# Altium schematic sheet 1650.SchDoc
size A4
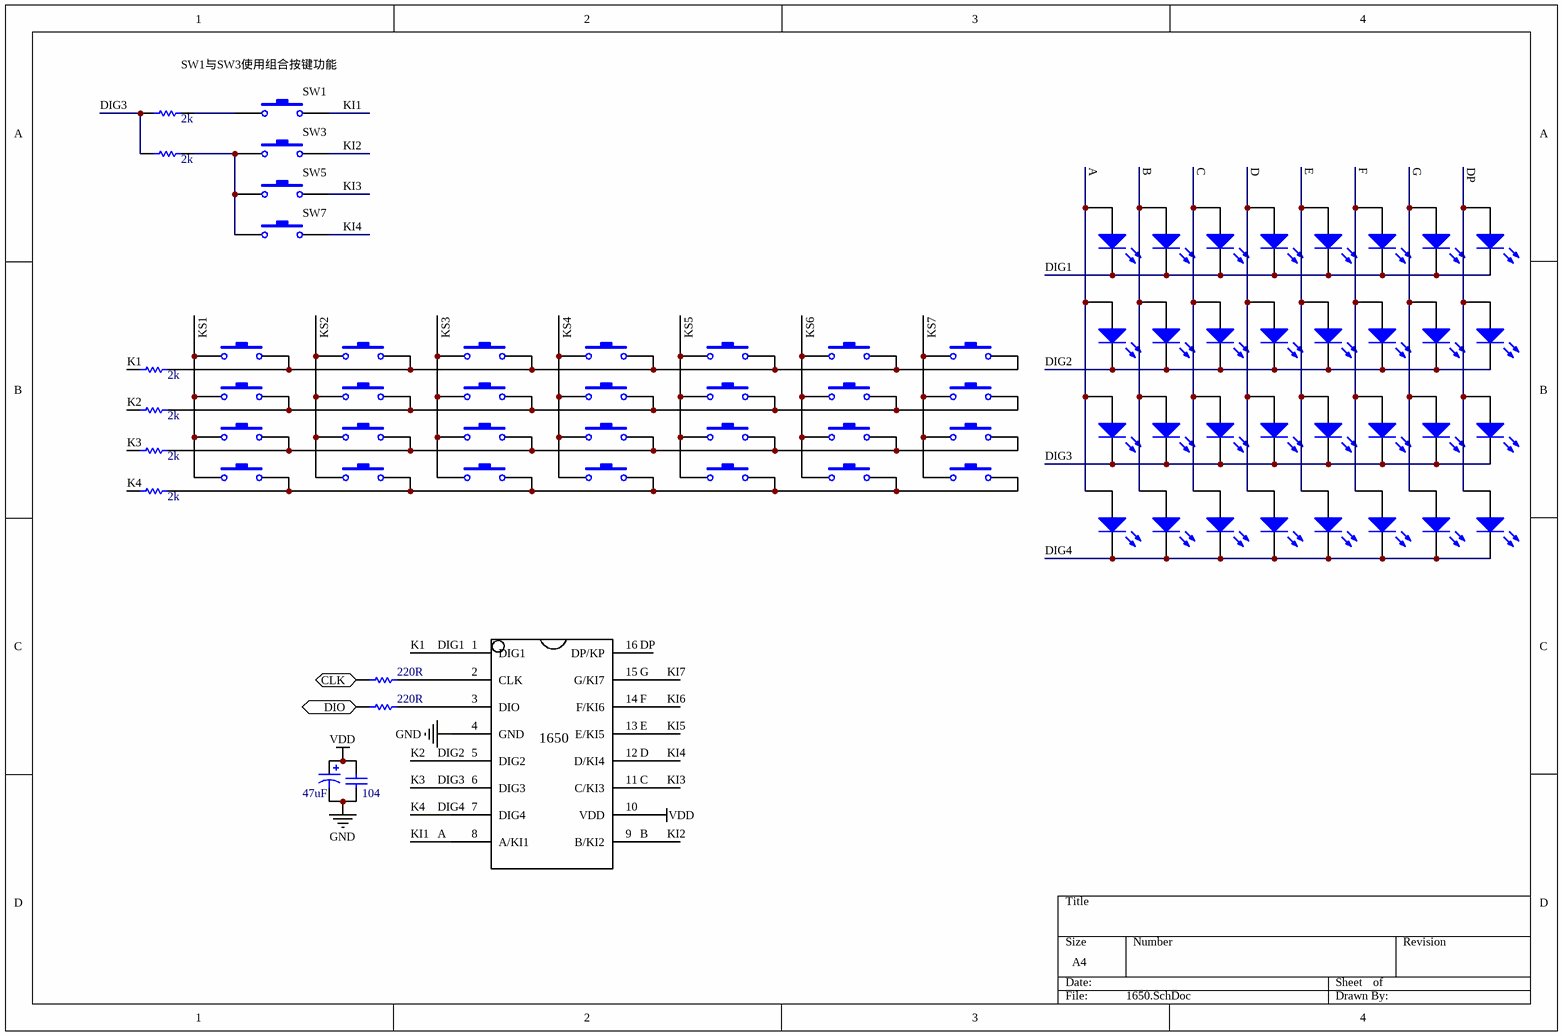
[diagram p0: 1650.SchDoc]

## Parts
(Parts that share a designator on the sheet are numbered #1, #2 ... from top to bottom, then left to right.)
*  Component_2  (value not drawn)
C6  value 104  [RAD-0.3]  (hidden comment: Cap)
C?  value 47uF  [RB7.6-15]  (hidden comment: Cap Pol1)
D?#1  LED0  [LED-0]  (value not drawn)
D?#2  LED0  [LED-0]  (value not drawn)
D?#3  LED0  [LED-0]  (value not drawn)
D?#4  LED0  [LED-0]  (value not drawn)
D?#5  LED0  [LED-0]  (value not drawn)
D?#6  LED0  [LED-0]  (value not drawn)
D?#7  LED0  [LED-0]  (value not drawn)
D?#8  LED0  [LED-0]  (value not drawn)
D?#9  LED0  [LED-0]  (value not drawn)
D?#10  LED0  [LED-0]  (value not drawn)
D?#11  LED0  [LED-0]  (value not drawn)
D?#12  LED0  [LED-0]  (value not drawn)
D?#13  LED0  [LED-0]  (value not drawn)
D?#14  LED0  [LED-0]  (value not drawn)
D?#15  LED0  [LED-0]  (value not drawn)
D?#16  LED0  [LED-0]  (value not drawn)
D?#17  LED0  [LED-0]  (value not drawn)
D?#18  LED0  [LED-0]  (value not drawn)
D?#19  LED0  [LED-0]  (value not drawn)
D?#20  LED0  [LED-0]  (value not drawn)
D?#21  LED0  [LED-0]  (value not drawn)
D?#22  LED0  [LED-0]  (value not drawn)
D?#23  LED0  [LED-0]  (value not drawn)
D?#24  LED0  [LED-0]  (value not drawn)
D?#25  LED0  [LED-0]  (value not drawn)
D?#26  LED0  [LED-0]  (value not drawn)
D?#27  LED0  [LED-0]  (value not drawn)
D?#28  LED0  [LED-0]  (value not drawn)
D?#29  LED0  [LED-0]  (value not drawn)
D?#30  LED0  [LED-0]  (value not drawn)
D?#31  LED0  [LED-0]  (value not drawn)
D?#32  LED0  [LED-0]  (value not drawn)
R?#1  value 2k  [AXIAL-0.3]  (hidden comment: Res1)
R?#2  value 2k  [AXIAL-0.3]  (hidden comment: Res1)
R?#3  value 2k  [AXIAL-0.3]  (hidden comment: Res1)
R?#4  value 2k  [AXIAL-0.3]  (hidden comment: Res1)
R?#5  value 2k  [AXIAL-0.3]  (hidden comment: Res1)
R?#6  value 2k  [AXIAL-0.3]  (hidden comment: Res1)
R?#7  value 220R  [AXIAL-0.3]  (hidden comment: Res1)
R?#8  value 220R  [AXIAL-0.3]  (hidden comment: Res1)
S?#1  SW-PB  [SPST-2]  (value not drawn)
S?#2  SW-PB  [SPST-2]  (value not drawn)
S?#3  SW-PB  [SPST-2]  (value not drawn)
S?#4  SW-PB  [SPST-2]  (value not drawn)
S?#5  SW-PB  [SPST-2]  (value not drawn)
S?#6  SW-PB  [SPST-2]  (value not drawn)
S?#7  SW-PB  [SPST-2]  (value not drawn)
S?#8  SW-PB  [SPST-2]  (value not drawn)
S?#9  SW-PB  [SPST-2]  (value not drawn)
S?#10  SW-PB  [SPST-2]  (value not drawn)
S?#11  SW-PB  [SPST-2]  (value not drawn)
S?#12  SW-PB  [SPST-2]  (value not drawn)
S?#13  SW-PB  [SPST-2]  (value not drawn)
S?#14  SW-PB  [SPST-2]  (value not drawn)
S?#15  SW-PB  [SPST-2]  (value not drawn)
S?#16  SW-PB  [SPST-2]  (value not drawn)
S?#17  SW-PB  [SPST-2]  (value not drawn)
S?#18  SW-PB  [SPST-2]  (value not drawn)
S?#19  SW-PB  [SPST-2]  (value not drawn)
S?#20  SW-PB  [SPST-2]  (value not drawn)
S?#21  SW-PB  [SPST-2]  (value not drawn)
S?#22  SW-PB  [SPST-2]  (value not drawn)
S?#23  SW-PB  [SPST-2]  (value not drawn)
S?#24  SW-PB  [SPST-2]  (value not drawn)
S?#25  SW-PB  [SPST-2]  (value not drawn)
S?#26  SW-PB  [SPST-2]  (value not drawn)
S?#27  SW-PB  [SPST-2]  (value not drawn)
S?#28  SW-PB  [SPST-2]  (value not drawn)
S?#29  SW-PB  [SPST-2]  (value not drawn)
S?#30  SW-PB  [SPST-2]  (value not drawn)
S?#31  SW-PB  [SPST-2]  (value not drawn)
S?#32  SW-PB  [SPST-2]  (value not drawn)

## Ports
CLK (in), DIO (bidir)

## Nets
GND: *.4(GND) C6.1 C?.2
VDD: *.10(VDD) C6.2 C?.1
A: *.8(A/KI1) S?#1.2  [also labelled KI1]
CLK: R?#7.1 ; port CLK
DIG1: *.1(DIG1) R?#3.1  [also labelled K1]
DIG2: *.5(DIG2) R?#4.1  [also labelled K2]
DIG3: *.6(DIG3) R?#1.1 R?#2.1 R?#5.1  [also labelled K3]
DIG4: *.7(DIG4) R?#6.1  [also labelled K4]
DIO: R?#8.1 ; port DIO
KI2: *.9(B/KI2) S?#2.2
KI3: *.11(C/KI3) S?#3.2
KI4: *.12(D/KI4) S?#4.2
KI5: *.13(E/KI5)
KI6: *.14(F/KI6)
KI7: *.15(G/KI7)
KS1: S?#5.1 S?#12.1 S?#19.1 S?#26.1
KS2: S?#6.1 S?#13.1 S?#20.1 S?#27.1
KS3: S?#7.1 S?#14.1 S?#21.1 S?#28.1
KS4: S?#8.1 S?#15.1 S?#22.1 S?#29.1
KS5: S?#9.1 S?#16.1 S?#23.1 S?#30.1
KS6: S?#10.1 S?#17.1 S?#24.1 S?#31.1
KS7: S?#11.1 S?#18.1 S?#25.1 S?#32.1
Net*_2: *.2(CLK) R?#7.2
Net*_3: *.3(DIO) R?#8.2
NetD?#1_1: D?#1.1(A) D?#9.1(A) D?#17.1(A) D?#25.1(A)
NetD?#1_2: D?#1.2(K) D?#2.2(K) D?#3.2(K) D?#4.2(K) D?#5.2(K) D?#6.2(K) D?#7.2(K) D?#8.2(K)
NetD?#2_1: D?#2.1(A) D?#10.1(A) D?#18.1(A) D?#26.1(A)
NetD?#3_1: D?#3.1(A) D?#11.1(A) D?#19.1(A) D?#27.1(A)
NetD?#4_1: D?#4.1(A) D?#12.1(A) D?#20.1(A) D?#28.1(A)
NetD?#5_1: D?#5.1(A) D?#13.1(A) D?#21.1(A) D?#29.1(A)
NetD?#6_1: D?#6.1(A) D?#14.1(A) D?#22.1(A) D?#30.1(A)
NetD?#7_1: D?#7.1(A) D?#15.1(A) D?#23.1(A) D?#31.1(A)
NetD?#8_1: D?#8.1(A) D?#16.1(A) D?#24.1(A) D?#32.1(A)
NetD?#9_2: D?#9.2(K) D?#10.2(K) D?#11.2(K) D?#12.2(K) D?#13.2(K) D?#14.2(K) D?#15.2(K) D?#16.2(K)
NetD?#17_2: D?#17.2(K) D?#18.2(K) D?#19.2(K) D?#20.2(K) D?#21.2(K) D?#22.2(K) D?#23.2(K) D?#24.2(K)
NetD?#25_2: D?#25.2(K) D?#26.2(K) D?#27.2(K) D?#28.2(K) D?#29.2(K) D?#30.2(K) D?#31.2(K) D?#32.2(K)
NetR?#1_2: R?#1.2 S?#1.1
NetR?#2_2: R?#2.2 S?#2.1 S?#3.1 S?#4.1
NetR?#3_2: R?#3.2 S?#5.2 S?#6.2 S?#7.2 S?#8.2 S?#9.2 S?#10.2 S?#11.2
NetR?#4_2: R?#4.2 S?#12.2 S?#13.2 S?#14.2 S?#15.2 S?#16.2 S?#17.2 S?#18.2
NetR?#5_2: R?#5.2 S?#19.2 S?#20.2 S?#21.2 S?#22.2 S?#23.2 S?#24.2 S?#25.2
NetR?#6_2: R?#6.2 S?#26.2 S?#27.2 S?#28.2 S?#29.2 S?#30.2 S?#31.2 S?#32.2

Not connected (* = marked no-connect by the designer): * 16(DP/KP)

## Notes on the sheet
- A
- B
- C
- D
- E
- F
- G
- DP
- (near D?#1) DIG1
- DIG2
- DIG3
- (near D?#25) DIG4
- Labels drawn without touching a wire or pin: B, C, D, DP, E, F, G, SW1, SW1与SW3使用组合按键功能, SW3, SW5, SW7

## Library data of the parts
C6 = Cap: Capacitor
C? = Cap Pol1: Polarized Capacitor (Radial)
D?#1-D?#32 = LED0: Typical INFRARED GaAs LED
R?#1-R?#8 = Res1: Resistor
S?#1-S?#32 = SW-PB: Switch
